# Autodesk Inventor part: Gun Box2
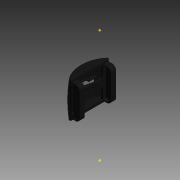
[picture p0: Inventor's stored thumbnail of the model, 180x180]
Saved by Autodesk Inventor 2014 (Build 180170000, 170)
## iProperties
Created: 2013-09
Part Number: Gun Box2
Material: Generic
Document SubType Name: Modeling
Designer: Joey Mason
Appearance: Black Control Joints
Mass: 578.978 g
Surface Area: 1651.69 cm^2
Volume: 578.978 cm^3
Density: 1 g/cm^3
d85: 5.200 in
d140: 10.700 in
d142: 10.700 in
d147: 0.000 ul
d148: 90.0 deg
d149: 0.000 ul
d150: 90.0 deg
d151: 0.000 ul
d152: 90.0 deg
d153: 0.000 ul
d154: 90.0 deg
d155: 0.000 ul
d156: 90.0 deg
d157: 0.000 ul
d158: 90.0 deg
d159: 0.000 ul
d160: 90.0 deg
d161: 3.300 in
d162: 6.600 in
d163: 11.000 in
d164: 0.0 deg
d165: 11.000 in
d166: 0.0 deg
d167: 1.932 in
d168: 11.000 in
d169: 0.0 deg
d170: 2.200 in
d171: 0.500 in
d172: 2.200 in
d173: 0.500 in
d174: 11.000 in
d175: 0.0 deg
d209: 0.627 in
d210: 2.400 in
d211: 6.500 in
d212: 11.000 in
d213: 0.0 deg
d218: 7.134 in
d219: 0.0 deg
d220: 0.200 in
d221: 0.0 deg
d222: 0.100 in
d223: 0.300 in
d224: 0.100 in
d225: 0.300 in
d226: 1.500 in
d227: 0.0 deg
d228: 1.000 in
d229: 1.000 in
d230: 135.0 deg
d231: 0.500 in
d232: 0.100 in
d233: 0.0 deg
d234: 1.000 in
d235: 0.500 in
d236: 135.0 deg
d237: 1.000 in
d238: 0.100 in
d239: 0.0 deg
d240: 0.300 in
d250: 0.700 in
d252: 0.300 in
d253: 0.300 in
d261: 1.000 in
d262: 1.000 in
d263: 2.100 in
d264: 0.0 deg
d276: 1.100 in
d277: 0.500 in
d278: 0.200 in
d279: 0.500 in
d280: 0.750 in
d281: 0.200 in
d282: 0.0 deg
d283: 0.200 in
d284: 0.0 deg
d285: 0.750 in
d286: 0.200 in
d287: 0.100 in
d288: 0.0 deg
d289: 0.100 in
d290: 0.0 deg
d291: 0.200 in
d292: 0.0 deg
d293: 0.200 in
d294: 0.0 deg
d295: 0.700 in
d296: 1.400 in
d297: 0.200 in
d298: 0.0 deg
d299: 0.750 in
d300: 6.200 in
d301: 0.0 deg
d302: 0.600 in
d303: 0.0 deg
d304: 0.600 in
d305: 0.0 deg
d306: 0.750 in
d307: 0.0 deg
d313: 0.600 in
d314: 0.300 in
d315: 0.0 deg
d316: 0.250 in
d317: 6.334 in
d318: 0.0 deg
d319: 0.200 in
d320: 0.0 deg
d321: 0.500 in
d326: 1.925 in
d327: 0.0 deg
d336: 0.100 in
d337: 0.250 in
d338: 0.100 in
d339: 0.250 in
d340: 1.100 in
d341: 0.240 in
d342: 1.100 in
d343: 0.240 in
d344: 1.450 in
d345: 0.0 deg
d346: 0.300 in
d347: 0.0 deg
d348: 0.300 in
d349: 0.0 deg
d364: 0.500 in
d365: 0.0 deg
d366: 2.200 in
d367: 0.700 in
d368: 1.400 in
d369: 0.500 in
d370: 0.0 deg
d371: 0.100 in
d372: 0.100 in
d373: 0.500 in
d374: 0.500 in
Author: Joey Mason
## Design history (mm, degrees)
workplane "Work Plane1"
sketch "Sketch18"
  geometry: 4 further points; 1 other entity
  constraints: 1 coincident, 4 other
  dimensions: "d140" = 271.78 distance of point (271.78, 0) point (0, 0)
sketch "Sketch19"
  geometry: 4 further points; 1 other entity
  constraints: 1 coincident, 4 other
  dimensions: "d142" = 271.78 distance of point (0, 0) point (0, 271.78)
sketch "Sketch21"
  geometry: 7 further points; 1 other entity
  constraints: 1 coincident, 2 other
sketch "Sketch22"
  geometry: 4 further points; 1 other entity
  constraints: 1 coincident, 4 other
workpoint "Work Point6"
workpoint "Work Point7"
sketch "Sketch24"
  geometry: 4 further points; 1 other entity
  constraints: 1 coincident, 4 other
loft "Loft3" sketch "Sketch24" dims count "d147" = 0, angle "d148" = 90 deg, count "d149" = 0, angle "d150" = 90 deg, count "d151" = 0, angle "d152" = 90 deg, count "d153" = 0, angle "d154" = 90 deg, count "d155" = 0, angle "d156" = 90 deg, count "d157" = 0, angle "d158" = 90 deg, count "d159" = 0, angle "d160" = 90 deg
sketch "Sketch25"
  geometry: L1 (0, 0)-(-93.98, 0); L2 (-93.98, 0)-(-93.98, 83.82); L3 (-93.98, 83.82)-(-93.98, -83.82); L4 (-93.98, -83.82)-(109.792, -83.82); L5 (109.792, -83.82)-(109.792, 83.82); L6 (109.792, 83.82)-(-93.98, 83.82); L7 (-93.98, 83.82)-(-93.98, -83.82); L8 (-93.98, 83.82)-(-56.43, 279.355); L9 (-56.43, 279.355)-(63.139, 301.853); L10 (63.139, 301.853)-(109.792, 83.82); L11 (109.792, -83.82)-(54.67, -311.124); L12 (54.67, -311.124)-(-84.397, -311.124); L13 (-84.397, -311.124)-(-93.98, -83.82); 3 further points; 1 other entity
  constraints: 26 end point, 3 vertical, 2 horizontal, 2 parallel, 2 perpendicular, 3 other
  dimensions: "d161" = 83.82 distance of L2.start L2.end; "d162" = 167.64 distance of L2.end L3.end
extrude "Extrusion9" cut sketch "Sketch25" stored distance "d163" = 279.4; taper "d164" = 0 deg
sketch "Sketch26"
  geometry: L1 (0, 91.936)-(0, -109.481); L2 (0, -109.481)-(134.746, -120.008); L3 (134.746, -120.008)-(134.746, 143.168); L4 (134.746, 143.168)-(0, 91.936); 1 further point
  constraints: 8 end point, 1 parallel, 1 vertical
extrude "Extrusion10" cut sketch "Sketch26" stored distance "d165" = 279.4; taper "d166" = 0 deg
sketch "Sketch27"
  geometry: L1 (-93.98, 0)-(-93.98, 113.525); L2 (-93.98, 113.525)-(-44.907, 113.525); L3 (-44.907, 113.525)-(61.796, 113.525); L4 (61.796, 113.525)-(61.796, -103.11); L5 (61.796, -103.11)-(-44.907, -103.11); L6 (-44.907, -103.11)-(-44.907, 113.525); L7 (-44.907, 113.525)-(-60.833, 113.525); L8 (0, 0)-(-60.96, 0); L9 (0, 0)-(0, -165.1); 4 further points; 2 other entities
  constraints: 18 end point, 3 horizontal, 3 parallel, 2 perpendicular, 2 vertical, 1 coincident, 1 point on line, 6 other
  dimensions: "d167" = 49.0728 distance of L1.end L2.end; "d209" = 15.9258 distance of L2.end L7.end; "d210" = 60.96 distance of L8.start L8.end; "d211" = 165.1 distance of L8.start L9.end
extrude "Extrusion11" cut sketch "Sketch27" stored distance "d168" = 279.4; taper "d169" = 0 deg
sketch "Sketch28"
  geometry: L1 (0, 167.64)-(204.463, 167.64) reference; L2 (102.231, 83.82)-(46.351, 83.82); L3 (46.351, 83.82)-(46.351, 96.52); L4 (102.231, 83.82)-(158.111, 83.82); L5 (158.111, 83.82)-(158.111, 71.12); L6 (158.111, 71.12)-(46.351, 71.12); L7 (46.351, 71.12)-(46.351, 96.52); L8 (46.351, 96.52)-(158.111, 96.52); L9 (158.111, 96.52)-(158.111, 71.12)
  constraints: 16 end point, 4 perpendicular, 3 parallel, 1 horizontal
  dimensions: "d170" = 55.88 distance of L2.start L2.end; "d171" = 12.7 distance of L2.end L3.end; "d172" = 55.88 distance of L2.start L4.end; "d173" = 12.7 distance of L4.end L5.end
extrude "Extrusion12" cut sketch "Sketch28" distance "d174" = 279.4; taper "d175" = 0 deg
extrude "Extrusion19" cut sketch "Sketch27" stored distance "d212" = 279.4; taper "d213" = 0 deg
workplane "Work Plane2"
sketch "Sketch36"
  geometry: L1 (-52.519, -119.695)-(-52.519, 119.695) reference; L2 (-52.519, 83.82)-(-52.519, -83.82); 2 further points; 1 other entity
  constraints: 2 end point, 2 point on line, 1 coincident, 4 other
extrude "Extrusion20" join sketch "Sketch36" stored distance "d218" = 181.2036; taper "d219" = 0 deg
sketch "Sketch37"
  geometry: L1 (0, 167.64)-(181.204, 167.64) reference; L2 (0, 0)-(0, 167.64) reference; L3 (181.204, 0)-(0, 0) reference; L4 (181.204, 167.64)-(181.204, 0) reference; 1 further point
extrude "Extrusion21" join sketch "Sketch37" distance "d220" = 5.08; taper "d221" = 0 deg
sketch "Sketch38"
  geometry: L1 (181.204, 167.64)-(0, 167.64) reference; L2 (0, 0)-(181.204, 0) reference; L3 (0, 167.64)-(2.54, 167.64); L4 (2.54, 167.64)-(2.54, 160.02); L5 (181.204, 0)-(178.664, 0); L6 (178.664, 0)-(178.664, 7.62); L7 (178.664, 7.62)-(2.54, 7.62); L8 (2.54, 7.62)-(2.54, 160.02); L9 (2.54, 160.02)-(178.664, 160.02); L10 (178.664, 160.02)-(178.664, 7.62); 1 further point
  constraints: 16 end point, 3 perpendicular, 2 parallel, 2 point on line, 1 horizontal
  dimensions: "d222" = 2.54 distance of L1.end L3.end; "d223" = 7.62 distance of L3.end L4.end; "d224" = 2.54 distance of L2.end L5.end; "d225" = 7.62 distance of L5.end L6.end
extrude "Extrusion22" join sketch "Sketch38" distance "d226" = 38.1; taper "d227" = 0 deg
sketch "Sketch39"
  geometry: L1 (47.439, -83.82)-(47.439, 83.82) reference; L2 (47.439, 83.82)-(47.439, 58.42); L3 (47.439, -83.82)-(47.439, -58.42); L4 (47.439, -58.42)-(56.42, -49.44); L5 (47.439, 58.42)-(56.42, 49.44); L6 (56.42, 49.44)-(56.42, -49.44)
  constraints: 10 end point, 2 point on line, 1 parallel, 1 perpendicular
  dimensions: "d228" = 25.4 distance of L1.end L2.end; "d229" = 25.4 distance of L1.start L3.end; "d230" = 135 deg angle of L3 L4; "d231" = 12.7 distance of L2.end L5.end
extrude "Extrusion23" cut sketch "Sketch39" distance "d232" = 2.54; taper "d233" = 0 deg
sketch "Sketch40"
  geometry: L1 (-47.439, 83.82)-(-47.439, -83.82) reference; L2 (-47.439, 83.82)-(-47.439, 58.42); L3 (-47.439, 58.42)-(-56.42, 49.44); L4 (-47.439, -83.82)-(-47.439, -58.42); L5 (-47.439, -58.42)-(-56.42, -49.44); L6 (-56.42, -49.44)-(-56.42, 49.44)
  constraints: 10 end point, 2 point on line, 1 parallel, 1 perpendicular
  dimensions: "d234" = 25.4 distance of L1.start L2.end; "d235" = 12.7 distance of L2.end L3.end; "d236" = 135 deg angle of L2 L3; "d237" = 25.4 distance of L1.end L4.end
extrude "Extrusion24" cut sketch "Sketch40" distance "d238" = 2.54; taper "d239" = 0 deg
fillet "Fillet4" dims "d240" = 7.62
sketch "Sketch41"
  geometry: L1 (-2.232, -117.764)-(-6.748, -113.248) reference; L2 (-2.232, -5.388)-(0, -3.156); L3 (0, 0)-(0, -3.156); L4 (5.08, -3.156)-(5.08, 9.544); L5 (5.08, -132.696)-(5.08, -119.996); L6 (-1.668, -13.061)-(2.848, -8.544); L7 (-1.668, -110.092)-(2.848, -114.608); L8 (-3.9, -104.703)-(-3.9, -18.449); L9 (-8.98, -107.86)-(-8.98, -15.293) reference; L10 (38.1, 9.544)-(33.02, 9.544); L11 (33.02, -3.156)-(33.02, -119.996); L12 (20.32, -132.696)-(5.08, -132.696); L13 (5.08, 9.544)-(20.32, 9.544); A1 r 7.62 centre (-7.62, 0) between (-2.232, -5.388) and (0, 0) reference; A2 r 7.62 centre (-2.54, -3.156) between (2.848, -8.544) and (5.08, -3.156); A3 r 7.62 centre (3.72, -18.449) between (-1.668, -13.061) and (-3.9, -18.449); A4 r 7.62 centre (3.72, -104.703) between (-3.9, -104.703) and (-1.668, -110.092); A5 r 7.62 centre (-2.54, -119.996) between (5.08, -119.996) and (2.848, -114.608); A6 r 12.7 centre (20.32, -3.156) between (33.02, -3.156) and (20.32, 9.544); A7 r 12.7 centre (20.32, -119.996) between (20.32, -132.696) and (33.02, -119.996); 3 further points
  constraints: 22 end point, 14 tangent, 12 point on circle, 6 centre point, 5 perpendicular, 3 equal radius, 3 point on line, 2 parallel, 1 collinear
  dimensions: "d250" = 17.78 distance of L5.start point (5.08, -114.916); "d252" = 7.62 radius of A2; "d253" = 7.62 radius of A3; "d278" = 5.08 distance of L10.start L10.end; "d279" = 12.7 radius of A6
workplane "Work Plane3"
sketch "Sketch42"
  geometry: L1 (5.08, -3.156)-(5.08, 9.544) reference; L2 (-1.668, -13.061)-(2.848, -8.544) reference; L3 (-3.9, -104.703)-(-3.9, -18.449) reference; L4 (2.848, -114.608)-(-1.668, -110.092) reference; L5 (5.08, -132.696)-(5.08, -119.996) reference; L6 (38.1, 8.483)-(38.1, -131.636) reference; L7 (5.08, 9.544)-(20.32, 9.544); L8 (33.02, -3.156)-(33.02, -119.996); L9 (20.32, -132.696)-(5.08, -132.696); A1 r 7.62 centre (-2.54, -3.156) between (2.848, -8.544) and (5.08, -3.156) reference; A2 r 7.62 centre (3.72, -18.449) between (-1.668, -13.061) and (-3.9, -18.449) reference; A3 r 7.62 centre (3.72, -104.703) between (-3.9, -104.703) and (-1.668, -110.092) reference; A4 r 7.62 centre (-2.54, -119.996) between (5.08, -119.996) and (2.848, -114.608) reference; A5 r 12.7 centre (20.32, -119.996) between (20.32, -132.696) and (33.02, -119.996); A6 r 12.7 centre (20.32, -3.156) between (33.02, -3.156) and (20.32, 9.544); 3 further points
  constraints: 6 end point, 4 point on circle, 4 tangent, 2 centre point, 2 perpendicular, 2 point on line, 1 equal radius, 1 parallel
  dimensions: "d276" = 27.94 distance of L1.end point (33.02, 9.544); "d277" = 12.7 radius of A5
sketch "Sketch45"
  geometry: L1 (2.54, 147.32)-(2.54, 160.02) reference; L2 (178.664, 20.32)-(178.664, 7.62) reference; L3 (178.664, 7.62)-(153.264, 7.62); L4 (2.54, 160.02)-(27.94, 160.02); L5 (27.94, 160.02)-(153.264, 160.02); L6 (153.264, 160.02)-(153.264, 7.62); L7 (153.264, 7.62)-(27.94, 7.62); L8 (27.94, 7.62)-(27.94, 160.02); 1 further point
  constraints: 12 end point, 3 parallel, 2 perpendicular, 1 horizontal
  dimensions: "d261" = 25.4 distance of L2.end L3.end; "d262" = 25.4 distance of L1.end L4.end
extrude "Extrusion28" cut sketch "Sketch45" distance "d263" = 53.34; taper "d264" = 0 deg
fillet "Fillet7" dims "d280" = 19.05
extrude "Extrusion33" cut sketch "Sketch41" distance "d281" = 5.08; taper "d282" = 0 deg
sketch "Sketch52"
  geometry: L1 (5.08, -17.78)-(5.08, -134.62) reference; L2 (42, -119.327)-(42, -33.073) reference; L3 (39.768, -27.685)-(35.252, -23.168) reference; L4 (33.02, -17.78)-(33.02, -5.08) reference; L5 (33.02, -5.08)-(17.78, -5.08) reference; L6 (35.252, -129.232)-(39.768, -124.715) reference; L7 (33.02, -147.32)-(33.02, -134.62) reference; L8 (17.78, -147.32)-(33.02, -147.32) reference; A1 r 7.62 centre (40.64, -17.78) between (33.02, -17.78) and (35.252, -23.168) reference; A2 r 12.7 centre (17.78, -17.78) between (17.78, -5.08) and (5.08, -17.78) reference; A3 r 7.62 centre (34.38, -33.073) between (42, -33.073) and (39.768, -27.685) reference; A4 r 7.62 centre (34.38, -119.327) between (39.768, -124.715) and (42, -119.327) reference; A5 r 7.62 centre (40.64, -134.62) between (35.252, -129.232) and (33.02, -134.62) reference; A6 r 12.7 centre (17.78, -134.62) between (5.08, -134.62) and (17.78, -147.32) reference; 1 further point
extrude "Extrusion34" cut sketch "Sketch52" distance "d283" = 5.08; taper "d284" = 0 deg
fillet "Fillet8" dims "d285" = 19.05
shell "Shell5" dims "d286" = 5.08
sketch "Sketch53"
  geometry: L1 (0, -125.324)-(0, 0) reference; L2 (0, 0)-(10.16, 0) reference; L3 (10.16, 0)-(10.16, 22.86) reference; L4 (3.92, 22.86)-(10.16, 22.86) reference; L5 (3.92, -148.184)-(10.16, -148.184) reference; L6 (10.16, -148.184)-(10.16, -125.324) reference; L7 (10.16, -125.324)-(0, -125.324) reference; 4 further points
  constraints: 2 vertical alignment, 2 other
extrude "Extrusion35" join sketch "Sketch53" distance "d287" = 2.54; taper "d288" = 0 deg
sketch "Sketch54"
  geometry: L1 (0, -125.324)-(0, 0) reference; L2 (10.16, 0)-(0, 0) reference; L3 (10.16, 0)-(10.16, 22.86) reference; L4 (3.92, 22.86)-(10.16, 22.86) reference; L5 (3.92, -148.184)-(10.16, -148.184) reference; L6 (10.16, -148.184)-(10.16, -125.324) reference; L7 (10.16, -125.324)-(0, -125.324) reference; 4 further points
  constraints: 2 vertical alignment, 2 other
extrude "Extrusion36" join sketch "Sketch54" distance "d289" = 2.54; taper "d290" = 0 deg
sketch "Sketch55"
  geometry: L1 (0, 125.324)-(0, 0) reference; L2 (0, 125.324)-(-5.08, 125.324) reference; L3 (-5.08, 148.184)-(-5.08, 125.324) reference; L4 (-11.32, 148.184)-(-5.08, 148.184) reference; L5 (-5.08, -22.86)-(-11.32, -22.86) reference; L6 (-5.08, 0)-(-5.08, -22.86) reference; L7 (0, 0)-(-5.08, 0) reference; 4 further points
  constraints: 2 vertical alignment, 2 other
extrude "Extrusion37" join sketch "Sketch55" distance "d291" = 5.08; taper "d292" = 0 deg
sketch "Sketch56"
  geometry: L1 (0, 125.324)-(0, 0) reference; L2 (0, 125.324)-(-5.08, 125.324) reference; L3 (-5.08, 148.184)-(-5.08, 125.324) reference; L4 (-11.32, 148.184)-(-5.08, 148.184) reference; L5 (-5.08, -22.86)-(-11.32, -22.86) reference; L6 (-5.08, 0)-(-5.08, -22.86) reference; L7 (0, 0)-(-5.08, 0) reference; 4 further points
  constraints: 2 vertical alignment, 2 other
extrude "Extrusion38" join sketch "Sketch56" distance "d293" = 5.08; taper "d294" = 0 deg
sketch "Sketch57"
  geometry: L1 (27.94, 26.67)-(27.94, 140.97) reference; L2 (27.94, 83.82)-(27.94, 101.6); L3 (27.94, 101.6)-(27.94, 66.04); L4 (153.264, 140.97)-(153.264, 26.67) reference; L5 (27.94, 101.6)-(153.264, 101.6); L6 (153.264, 101.6)-(153.264, 66.04); L7 (153.264, 66.04)-(27.94, 66.04); L8 (27.94, 66.04)-(27.94, 101.6); 1 further point
  constraints: 12 end point, 3 point on line, 2 parallel, 1 horizontal, 1 midpoint, 1 perpendicular
  dimensions: "d295" = 17.78 distance of L2.start L2.end; "d296" = 35.56 distance of L2.end L3.end
extrude "Extrusion39" join sketch "Sketch57" distance "d297" = 5.08; taper "d298" = 0 deg
fillet "Fillet9" dims "d299" = 19.05
sketch "Sketch58"
  geometry: L1 (33.02, -128.27)-(33.02, -13.97) reference; L2 (19.05, 0)-(19.05, -142.24); A1 r 13.97 centre (19.05, -13.97) between (33.02, -13.97) and (19.05, 0) reference; A2 r 13.97 centre (19.05, -128.27) between (19.05, -142.24) and (33.02, -128.27) reference; 1 further point
  constraints: 2 end point, 1 point on circle
extrude "Extrusion40" join sketch "Sketch58" distance "d300" = 157.48; taper "d301" = 0 deg
sketch "Sketch59"
  geometry: L1 (0, 20.32)-(0, 0) reference; L2 (0, 20.32)-(-125.324, 20.32) reference; L3 (-125.324, 0)-(-125.324, 20.32) reference; L4 (-106.274, -19.05)-(-19.05, -19.05) reference; L5 (-125.324, 20.32)-(0, 20.32); L6 (0, 20.32)-(0, 73.42); L7 (0, 73.42)-(-125.324, 73.42); L8 (-125.324, 73.42)-(-125.324, 20.32); A1 r 19.05 centre (-106.274, 0) between (-125.324, 0) and (-106.274, -19.05) reference; A2 r 19.05 centre (-19.05, 0) between (-19.05, -19.05) and (0, 0) reference; 1 further point
  constraints: 8 end point, 2 parallel, 1 horizontal, 1 perpendicular
extrude "Extrusion41" cut sketch "Sketch59" distance "d302" = 15.24; taper "d303" = 0 deg
sketch "Sketch60"
  geometry: L1 (0, 20.32)-(0, 0) reference; L2 (-19.05, 39.37)-(-106.274, 39.37) reference; L3 (-125.324, 0)-(-125.324, 20.32) reference; L4 (0, 0)-(-125.324, 0) reference; L5 (-125.324, 0)-(0, 0); L6 (0, 0)-(0, -78.296); L7 (0, -78.296)-(-125.324, -78.296); L8 (-125.324, -78.296)-(-125.324, 0); A1 r 19.05 centre (-19.05, 20.32) between (0, 20.32) and (-19.05, 39.37) reference; A2 r 19.05 centre (-106.274, 20.32) between (-106.274, 39.37) and (-125.324, 20.32) reference; 1 further point
  constraints: 8 end point, 2 parallel, 1 horizontal, 1 perpendicular
extrude "Extrusion42" cut sketch "Sketch60" distance "d304" = 15.24; taper "d305" = 0 deg
sketch "Sketch61"
  geometry: L1 (178.664, 26.67)-(178.664, 140.97) reference; L2 (46.99, 66.04)-(27.94, 66.04); L3 (134.214, 101.6)-(153.264, 101.6); L4 (153.264, 101.6)-(27.94, 101.6); L5 (27.94, 101.6)-(27.94, 140.97); L6 (27.94, 140.97)-(153.264, 140.97); L7 (153.264, 140.97)-(153.264, 101.6); L8 (153.264, 26.67)-(27.94, 26.67); L9 (27.94, 26.67)-(27.94, 66.04); L10 (27.94, 66.04)-(153.264, 66.04); L11 (153.264, 66.04)-(153.264, 26.67); A1 r 19.05 centre (134.214, 120.65) between (134.214, 101.6) and (153.264, 120.65) reference; A2 r 19.05 centre (46.99, 46.99) between (46.99, 66.04) and (27.94, 46.99) reference; 1 further point
  constraints: 20 end point, 5 parallel, 3 perpendicular, 2 horizontal, 2 tangent, 1 point on circle
extrude "Extrusion43" cut sketch "Sketch61" distance "d306" = 19.05; taper "d307" = 0 deg
workplane "Work Plane4"
sketch "Sketch63"
  geometry: L1 (27.94, 101.6)-(27.94, 140.97) reference; L2 (2.54, 140.97)-(27.94, 140.97) reference; L3 (2.54, 140.97)-(2.54, 26.67) reference; L4 (27.94, 26.67)-(2.54, 26.67) reference; L5 (153.264, 66.04)-(153.264, 26.67) reference; L6 (178.664, 26.67)-(153.264, 26.67) reference; L7 (178.664, 26.67)-(178.664, 140.97) reference; L8 (153.264, 140.97)-(178.664, 140.97) reference; L9 (27.94, 7.62)-(27.94, 26.67) reference; L10 (27.94, 26.67)-(2.54, 26.67) reference; L11 (2.54, 26.67)-(2.54, 7.62) reference; L12 (2.54, 7.62)-(27.94, 7.62) reference; L13 (2.54, 160.02)-(2.54, 140.97) reference; L14 (2.54, 140.97)-(27.94, 140.97) reference; L15 (27.94, 140.97)-(27.94, 160.02) reference; L16 (27.94, 160.02)-(2.54, 160.02) reference; L17 (153.264, 160.02)-(153.264, 140.97) reference; L18 (153.264, 140.97)-(178.664, 140.97) reference; L19 (178.664, 140.97)-(178.664, 160.02) reference; L20 (178.664, 160.02)-(153.264, 160.02) reference; L21 (178.664, 7.62)-(178.664, 26.67) reference; L22 (178.664, 26.67)-(153.264, 26.67) reference; L23 (153.264, 26.67)-(153.264, 7.62) reference; L24 (153.264, 7.62)-(178.664, 7.62) reference; L25 (27.94, 26.67)-(27.94, 66.04) reference; L26 (27.94, 66.04)-(153.264, 66.04) reference; L27 (153.264, 140.97)-(153.264, 101.6) reference; L28 (153.264, 101.6)-(27.94, 101.6) reference; 1 further point
extrude "Extrusion45" join sketch "Sketch63" distance "d314" = 7.62; taper "d315" = 0 deg
sketch "Sketch65"
  geometry: L1 (140.564, 142.24)-(140.564, 88.9) reference; L2 (140.564, 96.52)-(15.24, 96.52) reference; L3 (15.24, 88.9)-(15.24, 142.24) reference; L4 (0, 142.24)-(15.24, 142.24) reference; L5 (0, 0)-(0, 142.24) reference; L6 (15.24, 0)-(0, 0) reference; L7 (15.24, 0)-(15.24, 142.24) reference; L8 (15.24, 45.72)-(140.564, 45.72) reference; L9 (140.564, 142.24)-(140.564, 0) reference; L10 (155.804, 0)-(140.564, 0) reference; L11 (155.804, 142.24)-(155.804, 0) reference; L12 (140.564, 142.24)-(155.804, 142.24) reference; A1 r 19.05 centre (121.514, 115.57) between (121.514, 96.52) and (140.564, 115.57) reference; A2 r 19.05 centre (34.29, 115.57) between (15.24, 115.57) and (34.29, 96.52) reference; A3 r 19.05 centre (34.29, 26.67) between (34.29, 45.72) and (15.24, 26.67) reference; A4 r 19.05 centre (121.514, 26.67) between (140.564, 26.67) and (121.514, 45.72) reference; 1 further point
sketch "Sketch64"
  geometry: L1 (20.32, -132.696)-(5.08, -132.696) reference; L2 (5.08, 9.544)-(20.32, 9.544) reference; L3 (19.05, -132.696)-(19.05, 9.544) reference; L4 (19.05, -132.696)-(25.4, -132.696); L5 (25.4, -132.696)-(25.4, -131.636); L6 (25.4, -131.636)-(25.4, 8.483); A1 r 12.7 centre (20.32, -119.996) between (20.32, -132.696) and (33.02, -119.996) reference; A2 r 12.7 centre (20.32, -3.156) between (33.02, -3.156) and (20.32, 9.544) reference; 1 further point
  constraints: 6 end point, 2 perpendicular, 2 point on circle, 1 parallel
  dimensions: "d316" = 6.35 distance of L3.start L4.end
extrude "Extrusion46" cut sketch "Sketch64" distance "d317" = 160.8836; taper "d318" = 0 deg
extrude "Extrusion47" join sketch "Sketch64" distance "d319" = 5.08; taper "d320" = 0 deg
fillet "Fillet11" dims "d321" = 12.7
sketch "Sketch66"
  geometry: L1 (140.564, 101.6)-(40.64, 101.6) reference; L2 (90.602, 83.82)-(93.142, 83.82); L3 (93.142, 83.82)-(99.492, 83.82); L4 (90.602, 83.82)-(88.062, 83.82); L5 (88.062, 83.82)-(81.712, 83.82); L6 (153.264, 140.97)-(153.264, 114.3) reference; L7 (81.712, 83.82)-(79.172, 83.82); L8 (99.492, 83.82)-(102.032, 83.82); C1 r 6.35 at (79.172, 83.82); C2 r 6.35 at (102.032, 83.82)
  constraints: 12 end point, 4 collinear, 2 centre point, 2 coincident, 1 parallel, 1 perpendicular
  dimensions: "d336" = 2.54 distance of L2.start L2.end; "d337" = 6.35 distance of L2.end L3.end; "d338" = 2.54 distance of L2.start L4.end; "d339" = 6.35 distance of L4.end L5.end; "d371" = 2.54 distance of L5.end L7.end; "d372" = 2.54 distance of L3.end L8.end; "d373" = 12.7 diameter of C1; "d374" = 12.7 diameter of C2
extrude "Extrusion48" cut sketch "Sketch66" distance "d326" = 48.9; taper "d327" = 0 deg
sketch "Sketch71"
  geometry: L1 (15.62, 0)-(0, 0) reference; L2 (0, 0)-(0, -27.94); L3 (0, -111.76)-(0, -83.82); C1 r 3.048 at (0, -27.94); C2 r 3.048 at (0, -83.82); 2 further points
  constraints: 4 end point, 2 centre point, 2 coincident, 1 collinear, 1 perpendicular
  dimensions: "d340" = 27.94 distance of L1.end L2.end; "d341" = 6.096 diameter of C1; "d342" = 27.94 distance of L3.start L3.end; "d343" = 6.096 diameter of C2
extrude "Extrusion50" cut sketch "Sketch71" distance "d344" = 36.83; taper "d345" = 0 deg
sketch "Sketch72"
  geometry: L1 (34.722, 71.12)-(34.722, 66.04) reference; L2 (34.722, 66.04)-(146.482, 66.04) reference; L3 (146.482, 66.04)-(146.482, 71.12) reference; L4 (34.722, 71.12)-(146.482, 71.12) reference; 1 further point
sketch "Sketch73"
  geometry: L1 (34.722, 101.6)-(34.722, 96.52) reference; L2 (146.482, 96.52)-(34.722, 96.52) reference; L3 (146.482, 96.52)-(146.482, 101.6) reference; L4 (146.482, 101.6)-(34.722, 101.6) reference; 1 further point
extrude "Extrusion51" cut sketch "Sketch73" distance "d346" = 7.62; taper "d347" = 0 deg
extrude "Extrusion52" cut sketch "Sketch72" distance "d348" = 7.62; taper "d349" = 0 deg
sketch "Sketch82"
  geometry: L1 (40.64, 66.04)-(140.564, 66.04) reference; L2 (140.564, 101.6)-(40.64, 101.6) reference; L3 (27.94, 114.3)-(27.94, 53.34); L4 (27.94, 114.3)-(153.264, 114.3); L5 (153.264, 114.3)-(153.264, 53.34); L6 (153.264, 53.34)-(27.94, 53.34); L7 (27.94, 53.34)-(27.94, 114.3); A1 r 12.7 centre (40.64, 53.34) between (40.64, 66.04) and (27.94, 53.34) reference; A2 r 12.7 centre (140.564, 53.34) between (153.264, 53.34) and (140.564, 66.04) reference; A3 r 12.7 centre (40.64, 114.3) between (27.94, 114.3) and (40.64, 101.6) reference; 1 further point
  constraints: 10 end point, 2 parallel, 2 perpendicular, 2 tangent, 1 horizontal
extrude "Extrusion60" cut sketch "Sketch82" distance "d364" = 12.7; taper "d365" = 0 deg
sketch "Sketch83"
  geometry: L1 (34.722, 101.6)-(146.482, 101.6) reference; L2 (34.722, 101.6)-(90.602, 101.6); L3 (90.602, 101.6)-(72.822, 101.6); L4 (72.822, 101.6)-(108.382, 101.6); L5 (146.482, 66.04)-(34.722, 66.04) reference; L6 (72.822, 101.6)-(108.382, 101.6); L7 (108.382, 101.6)-(108.382, 66.04); L8 (108.382, 66.04)-(72.822, 66.04); L9 (72.822, 66.04)-(72.822, 101.6); 1 further point
  constraints: 14 end point, 3 point on line, 2 parallel, 1 horizontal, 1 midpoint, 1 perpendicular
  dimensions: "d366" = 55.88 distance of L1.start L2.end; "d367" = 17.78 distance of L2.end L3.end; "d368" = 35.56 distance of L3.end L4.end
extrude "Extrusion61" cut sketch "Sketch83" distance "d369" = 12.7; taper "d370" = 0 deg
body "Solid3"
node "Projected Loop2"
node "Projected Loop3"
node "Projected Loop4"
node "Projected Loop5"
node "Projected Loop6"
other parameters: "d85" = 132.08, "d313" = 15.24
